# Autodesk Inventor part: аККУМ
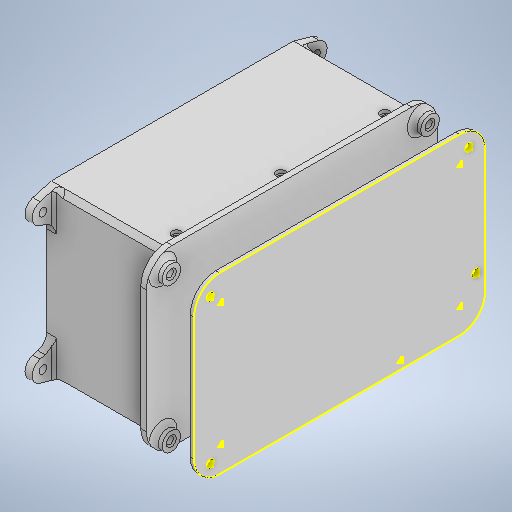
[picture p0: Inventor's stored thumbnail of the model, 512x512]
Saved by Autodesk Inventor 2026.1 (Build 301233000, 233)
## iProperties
Created: 2026-01
Part Number: аККУМ
Material: Типовые
Document SubType Name: Modeling
Designer: Yury Melnikov
Density: 1 g/cm^3
Appearance: По умолчанию
Author: Yury Melnikov
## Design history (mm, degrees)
sketch "Эскиз1"
  geometry: L1 (0, 0)-(65, 0); L2 (65, 0)-(65, 75); L3 (65, 75)-(0, 75); L4 (0, 75)-(0, 0); L5 (65, 0)-(0, 0); L6 (0, 0)-(0, -25); L7 (0, -25)-(65, -25); L8 (65, -25)-(65, 0); 1 further point
  constraints: 16 end point, 4 parallel, 2 horizontal, 2 perpendicular, 1 collinear
  dimensions: "d0" = 75 distance of L1.end L2.end; "d1" = 65 distance of L2.end L3.end; "d4" = 25 distance of L6.end L5.end
extrude "Выдавливание1" new body sketch "Эскиз1" distance "d2" = 45; taper "d3" = 0 deg
feature "Оболочка1" dims "d5" = 2.4
chamfer "Фаска1" distance "d9" = 2; stored, may be unused: second distance "d10" = 2, angle "d11" = 45 deg
sketch "Эскиз3"
  geometry: L1 (25, 63)-(25, 2) reference; L2 (23, 0)-(25, 2) reference; L3 (23, 0)-(-73, 0) reference; L4 (-75, 2)-(-73, 0) reference; L5 (-75, 2)-(-75, 63) reference; L6 (-73, 65)-(-75, 63) reference; L7 (-73, 65)-(23, 65) reference; L8 (25, 63)-(23, 65) reference; L9 (-75.4, -2.4)-(-77.4, -0.4) reference; L10 (-75.4, -2.4)-(25.4, -2.4) reference; L11 (27.4, -0.4)-(25.4, -2.4) reference; L12 (27.4, -0.4)-(27.4, 65.4) reference; L13 (25.4, 67.4)-(27.4, 65.4) reference; L14 (25.4, 67.4)-(-75.4, 67.4) reference; L15 (-77.4, 65.4)-(-75.4, 67.4) reference; L16 (-77.4, 65.4)-(-77.4, -0.4) reference; L17 (-72.917, 0.2)-(22.917, 0.2); L18 (22.917, 0.2)-(24.8, 2.083); L19 (24.8, 2.083)-(24.8, 62.917); L20 (24.8, 62.917)-(22.917, 64.8); L21 (22.917, 64.8)-(-72.917, 64.8); L22 (-72.917, 64.8)-(-74.8, 62.917); L23 (-74.8, 62.917)-(-74.8, 2.083); L24 (-74.8, 2.083)-(-72.917, 0.2); L25 (22.089, 2.2)-(-72.089, 2.2); L26 (-72.089, 2.2)-(-72.8, 2.911); L27 (-72.8, 2.911)-(-72.8, 62.089); L28 (-72.8, 62.089)-(-72.089, 62.8); L29 (-72.089, 62.8)-(22.089, 62.8); L30 (22.089, 62.8)-(22.8, 62.089); L31 (22.8, 62.089)-(22.8, 2.911); L32 (22.8, 2.911)-(22.089, 2.2); 1 further point
  constraints: 32 end point, 14 other
  dimensions: "d12" = 0.2 distance between parallel lines of L3 L17; "d13" = 2 distance between parallel lines of L17 L25
extrude "Выдавливание3" new body sketch "Эскиз3" distance "d14" = 5; taper "d15" = 0 deg
sketch "Эскиз4"
  geometry: L1 (25, 63)-(25, 2) reference; L2 (23, 0)-(25, 2) reference; L3 (23, 0)-(-73, 0) reference; L4 (-75, 2)-(-73, 0) reference; L5 (-75, 2)-(-75, 63) reference; L6 (-73, 65)-(-75, 63) reference; L7 (-73, 65)-(23, 65) reference; L8 (25, 63)-(23, 65) reference; L9 (-75.4, -2.4)-(-77.4, -0.4) reference; L10 (-75.4, -2.4)-(25.4, -2.4) reference; L11 (27.4, -0.4)-(25.4, -2.4) reference; L12 (27.4, -0.4)-(27.4, 65.4) reference; L13 (25.4, 67.4)-(27.4, 65.4) reference; L14 (25.4, 67.4)-(-75.4, 67.4) reference; L15 (-77.4, 65.4)-(-75.4, 67.4) reference; L16 (-77.4, 65.4)-(-77.4, -0.4) reference; 1 further point
extrude "Выдавливание4" join sketch "Эскиз4" distance "d16" = 2.4; taper "d17" = 0 deg
chamfer "Фаска2" distance "d18" = 2; stored, may be unused: second distance "d19" = 2, angle "d20" = 45 deg
chamfer "Фаска3" distance "d21" = 1.5; stored, may be unused: second distance "d22" = 2, angle "d23" = 45 deg
chamfer "Фаска4" distance "d24" = 0.5; stored, may be unused: second distance "d25" = 2, angle "d26" = 45 deg
sketch "Эскиз5"
  geometry: L1 (40.9, -98.317)-(40.9, -2.483) reference; L2 (45.4, -98.317)-(40.9, -98.317) reference; L3 (45.4, -2.483)-(45.4, -98.317) reference; L4 (45.4, -2.483)-(40.9, -2.483) reference; L5 (43.15, -93.817)-(43.15, -50.4); L6 (43.15, -50.4)-(43.15, -6.983); C1 r 0.75 at (43.15, -93.817); C2 r 0.75 at (43.15, -50.4); C3 r 0.75 at (43.15, -6.983); 3 further points
  constraints: 4 end point, 3 centre point, 2 collinear, 2 equal radius, 2 midpoint, 1 horizontal alignment, 1 point on line, 1 vertical
  dimensions: "d27" = 1.5 diameter of C2; "d28" = 4.5 distance from line of L2 L5.start
extrude "Выдавливание5" cut sketch "Эскиз5" distance "d29" = 75; taper "d30" = 0 deg
sketch "Эскиз8"
  geometry: L1 (-2.4, -2.4)-(98.4, -2.4) reference; L2 (-2.4, -2.4)-(72.6, -2.4); L3 (72.6, -2.4)-(72.6, 62.6); L4 (72.6, 62.6)-(-2.4, 62.6); L5 (-2.4, 62.6)-(-2.4, -2.4); L6 (74.6, -2.4)-(74.6, 62.6); L7 (72.6, -2.4)-(74.6, -2.4); L8 (72.6, 62.6)-(74.6, 62.6); L9 (74.6, 55.993)-(72.6, 55.993); L10 (72.6, 55.993)-(72.6, 64.22); L11 (72.6, 64.22)-(74.6, 64.22); L12 (74.6, 64.22)-(74.6, 55.993); 3 further points
  constraints: 22 end point, 5 parallel, 4 point on line, 3 horizontal, 2 perpendicular, 1 vertical
  dimensions: "d31" = 65 distance of L2.end L3.end; "d32" = 75 distance between parallel lines of L5 L3; "d33" = 2 distance between parallel lines of L6 L3
extrude "Выдавливание6" join sketch "Эскиз8" distance "d34" = 40; taper "d35" = 0 deg
chamfer "Фаска5" distance "d36" = 1; stored, may be unused: second distance "d37" = 2, angle "d38" = 45 deg
sketch "Эскиз9"
  geometry: L1 (0, 0)-(0, 65.8) reference; L2 (47.4, 0)-(0, 0) reference; L3 (15, 15)-(15, 50.8); C1 r 3 at (15, 15); C2 r 15 at (15, 15); C3 r 6.1 at (15, 50.8); 4 further points
  constraints: 3 centre point, 2 end point, 2 midpoint, 2 tangent, 1 coincident, 1 horizontal alignment, 1 vertical, 1 vertical alignment
  dimensions: "d39" = 6 diameter of C1; "d40" = 30 diameter of C2; "d41" = 12.2 diameter of C3
extrude "Выдавливание7" cut sketch "Эскиз9" distance "d42" = 3; taper "d43" = 0 deg
sketch "Эскиз10"
  geometry: L1 (40.4, -74)-(2.4, -74) reference; L2 (40.4, -74)-(40.4, -78) reference; L3 (2.4, -78)-(40.4, -78) reference; L4 (2.4, -98.4)-(2.4, -78) reference; L5 (45.4, -98.4)-(2.4, -98.4) reference; L6 (45.4, -2.4)-(45.4, -98.4) reference; L7 (2.4, -2.4)-(45.4, -2.4) reference; L8 (2.4, -74)-(2.4, -2.4) reference; L9 (31.65, -83.95)-(16.15, -83.95); L10 (16.15, -83.95)-(16.15, -92.45); L11 (16.15, -92.45)-(31.65, -92.45); L12 (31.65, -92.45)-(31.65, -83.95); C1 r 0.75 at (43.15, -93.817) reference; C2 r 0.75 at (43.15, -50.4) reference; C3 r 0.75 at (43.15, -6.983) reference; 5 further points
  constraints: 8 end point, 4 midpoint, 2 parallel, 1 horizontal, 1 horizontal alignment, 1 perpendicular, 1 vertical alignment
  dimensions: "d44" = 15.5 distance of L11.end L10.end; "d45" = 8.5 distance of L10.end L9.end
extrude "Выдавливание8" cut sketch "Эскиз10" distance "d46" = 3; taper "d47" = 0 deg
chamfer "Фаска6" distance "d48" = 0.7; stored, may be unused: second distance "d49" = 2, angle "d50" = 45 deg
chamfer "Фаска7" distance "d51" = 0.5; stored, may be unused: second distance "d52" = 2, angle "d53" = 45 deg
sketch "Эскиз11"
  geometry: C1 r 0.75 at (43.15, -6.983) reference; C2 r 0.75 at (43.15, -50.4) reference; C3 r 0.75 at (43.15, -93.817) reference; C4 r 2 at (43.15, -6.983); C5 r 2 at (43.15, -50.4); C6 r 2 at (43.15, -93.817); 1 further point
  constraints: 3 centre point, 2 equal radius
  dimensions: "d54" = 4 diameter of C4
extrude "Выдавливание9" cut sketch "Эскиз11" distance "d55" = 1.4; taper "d56" = 0 deg
chamfer "Фаска8" distance "d57" = 0.5; stored, may be unused: second distance "d58" = 2, angle "d59" = 45 deg
node "РабПлоскость2"
mirror "Зеркальное отражение1"
node "РабПлоскость3"
sketch "Эскиз12"
  geometry: L1 (2, 61)-(2, 0) reference; L2 (2, 0)-(2, 61) reference; L3 (2, 9.6)-(2, 15.6) reference; L4 (2, 42.3)-(2, 54.5) reference; L5 (2, 49)-(-4.5, 49); L6 (-4.5, 49)-(-4.5, 42); L7 (-4.5, 42)-(-2.5, 42); L8 (-2.5, 42)-(-2.5, 47); L9 (-2.5, 47)-(2, 47); L10 (-2.5, 47)-(-2.5, 49); L11 (2, 30.5)-(16.292, 30.5); L12 (2, 18.7)-(2, 6.5); L13 (2, 12)-(-4.5, 12); L14 (-4.5, 12)-(-4.5, 19); L15 (-4.5, 19)-(-2.5, 19); L16 (-2.5, 19)-(-2.5, 14); L17 (-2.5, 14)-(2, 14); L18 (-2.5, 14)-(-2.5, 12); 6 further points
  constraints: 28 end point, 9 symmetric about line, 8 point on line, 3 horizontal, 3 perpendicular, 2 midpoint, 1 vertical
  dimensions: "d62" = 5 distance of L7.end L8.end; "d63" = 2 distance of L6.end L7.end; "d64" = 4.5 distance of L8.end L9.end; "d65" = 33 distance from line of L17 point (-0.25, 47)
extrude "Выдавливание10" join sketch "Эскиз12" distance "d66" = 6; taper "d67" = 0 deg
sketch "Эскиз13"
  geometry: L1 (37, 16.4)-(37, 21.4) reference; L2 (37, 21.4)-(31, 21.4) reference; L3 (31, 16.4)-(31, 21.4) reference; L4 (37, 16.4)-(31, 16.4) reference; L5 (37, 44.4)-(37, 49.4) reference; L6 (37, 49.4)-(31, 49.4) reference; L7 (31, 44.4)-(31, 49.4) reference; L8 (37, 44.4)-(31, 44.4) reference; L9 (27.35, 16.65)-(40.65, 16.65); L10 (40.65, 16.65)-(40.65, 49.15); L11 (40.65, 49.15)-(27.35, 49.15); L12 (27.35, 49.15)-(27.35, 16.65); L13 (31, 21.4)-(31, 44.4); C1 r 1.65 at (30.35, 41.15); C2 r 1.65 at (30.35, 36.15); C3 r 1.65 at (30.35, 31.15); C4 r 1.65 at (30.35, 26.15); C5 r 2.1 at (35.65, 41.65); 5 further points
  constraints: 10 end point, 5 centre point, 4 midpoint, 2 parallel, 2 vertical, 1 horizontal, 1 horizontal alignment, 1 perpendicular, 1 vertical alignment, 6 other
  dimensions: "d68" = 32.5 distance of L11.end L9.start; "d69" = 13.3 distance of L9.start L9.end; "d70" = 3 horizontal distance of C1.centre L11.end; "d71" = 8 vertical distance of L11.end C1.centre; "d72" = 3.3 diameter of C1; "d75" = 5 distance of C1.centre C2.centre; "d80" = 4.2 diameter of C5; "d81" = 7.5 vertical distance of L10.end C5.centre; "d82" = 5 distance from line of L10 C5.centre
extrude "Выдавливание11" cut sketch "Эскиз13" distance "d83" = 6; taper "d84" = 0 deg
chamfer "Фаска9" distance "d85" = 0.5; stored, may be unused: second distance "d86" = 2, angle "d87" = 45 deg
chamfer "Фаска10" distance "d88" = 3; stored, may be unused: second distance "d89" = 2, angle "d90" = 45 deg
sketch "Эскиз15"
  geometry: L1 (-77.4, 67.4)-(27.4, 67.4); L2 (27.4, 67.4)-(27.4, -2.4); L3 (27.4, -2.4)-(-77.4, -2.4); L4 (-77.4, -2.4)-(-77.4, 67.4); L5 (25.4, 67.4)-(-75.4, 67.4) reference; L6 (-77.4, 65.4)-(-77.4, -0.4) reference; L7 (-75.4, -2.4)-(25.4, -2.4) reference; L8 (27.4, -0.4)-(27.4, 65.4) reference; 1 further point
  constraints: 8 end point, 4 collinear, 2 parallel, 1 horizontal, 1 perpendicular
  dimensions: "d99" = 104.8 distance of L1.start L1.end (derived); "d100" = 69.8 distance of L1.end L2.end (derived)
sketch "Эскиз16"
  geometry: L1 (-2.4, -2)-(47.4, -2); L2 (47.4, -2)-(47.4, 67.8); L3 (47.4, 67.8)-(-2.4, 67.8); L4 (-2.4, 67.8)-(-2.4, -2); L5 (47.4, 67.8)-(0, 67.8) reference; L6 (47.4, 0)-(47.4, 65.8) reference; L7 (-2.4, 64.972)-(-2.4, 0.828) reference; L8 (0, -2)-(47.4, -2) reference; 3 further points
  constraints: 8 end point, 4 collinear, 2 parallel, 1 horizontal, 1 perpendicular
  dimensions: "d101" = 49.8 distance of L2.end L3.end (derived)
sketch "Эскиз17"
  geometry: L1 (15.4, 55.4)-(15.4, 9.6); L2 (15.4, 9.6)-(-65.4, 32.5); L3 (27.4, -0.4)-(27.4, 65.4) reference; L4 (-74.572, 65.4)-(24.572, 65.4) reference; L5 (25.4, 64.572)-(25.4, 0.428) reference; L6 (24.572, -0.4)-(-74.572, -0.4) reference; L7 (-75.4, 0.428)-(-75.4, 64.572) reference; C1 r 2 at (-65.4, 32.5); C2 r 2 at (15.4, 55.4); C3 r 2 at (15.4, 9.6); C4 r 10 at (15.4, 55.4); C5 r 10 at (15.4, 9.6); C6 r 10 at (-65.4, 32.5); 3 further points
  constraints: 6 centre point, 4 end point, 4 tangent, 3 coincident, 3 equal radius, 2 horizontal alignment, 2 midpoint, 1 vertical, 1 vertical alignment
  dimensions: "d102" = 4 diameter of C1; "d103" = 8 distance edge to line of C1 L7
extrude "Выдавливание13" cut sketch "Эскиз17" distance "d104" = 10; taper "d105" = 0 deg
sketch "Эскиз20"
  geometry: L1 (-25.4, 67.4)-(75.4, 67.4) reference; L2 (-27.4, -2.4)-(-27.4, 67.4) reference; L3 (-47.022, 65.4)-(-10.668, 65.4); L4 (-58.591, -0.4)-(13.104, -0.4); L5 (77.4, 65.4)-(77.4, -0.4) reference; L6 (75.4, 67.4)-(83.117, 65.232); L7 (83.117, 56.568)-(77.4, 54.962); L8 (83.117, 65.232)-(77.4, 66.838); L9 (25, 67.4)-(25, 80.723); L10 (77.4, 32.5)-(86.793, 32.5); L11 (-25.4, 67.4)-(-33.117, 65.232); L12 (-33.117, 56.568)-(-27.4, 54.962); L13 (-47.022, -0.4)-(-10.668, -0.4); L14 (-33.117, 8.432)-(-27.4, 10.038); L15 (-25.4, -2.4)-(-33.117, -0.232); L16 (-25.4, -2.4)-(75.4, -2.4); L17 (83.117, 8.432)-(77.4, 10.038); L18 (83.117, -0.232)-(77.4, -1.838); L19 (75.4, -2.4)-(83.117, -0.232); L20 (-27.4, 65.4)-(-25.4, 67.4) reference; L21 (-27.4, -0.4)-(-27.4, 65.4) reference; L22 (-25.4, -2.4)-(-27.4, -0.4) reference; L23 (75.4, -2.4)-(-25.4, -2.4) reference; L24 (77.4, -0.4)-(75.4, -2.4) reference; L25 (77.4, 65.4)-(77.4, -0.4) reference; L26 (75.4, 67.4)-(77.4, 65.4) reference; L27 (-25.4, 67.4)-(75.4, 67.4) reference; C1 r 1.65 at (-31.9, 60.9); C2 r 4.5 at (-31.9, 60.9); C3 r 1.65 at (81.9, 60.9); C4 r 1.65 at (-31.9, 4.1); C5 r 4.5 at (-31.9, 4.1); C6 r 1.65 at (81.9, 4.1); C7 r 4.5 at (81.9, 4.1); C8 r 4.5 at (-31.9, 4.1); C9 r 1.65 at (-31.9, 4.1); C10 r 1.65 at (81.9, 4.1); A1 r 4.5 centre (81.9, 60.9) between (83.117, 56.568) and (83.117, 65.232); A2 r 5.938 centre (77.4, 60.9) between (77.4, 66.838) and (77.4, 54.962); A3 r 4.5 centre (81.9, 4.1) between (83.117, 8.432) and (83.117, -0.232); A4 r 5.938 centre (77.4, 4.1) between (77.4, -1.838) and (77.4, 10.038); 21 further points
  constraints: 32 end point, 20 symmetric about line, 14 centre point, 10 point on circle, 8 point on line, 6 coincident, 6 tangent, 4 horizontal, 2 midpoint, 2 vertical, 1 collinear, 17 other
  dimensions: "d122" = 3.3 diameter of C1; "d123" = 9 diameter of C2; "d126" = 113.8 distance of C1.centre C3.centre (derived); "d129" = 56.8 distance of C1.centre C4.centre (derived)
extrude "Выдавливание16" join sketch "Эскиз20" distance "d132" = 3; taper "d133" = 0 deg
fillet "Сопряжение1" dims "d134" = 5
node "РабПлоскость5"
chamfer "Фаска12" distance "d135" = 1; stored, may be unused: second distance "d136" = 2, angle "d137" = 45 deg
sketch "Эскиз21"
  geometry: L1 (-31.9, 60.9)-(81.9, 60.9); L2 (81.9, 60.9)-(81.9, 4.1); L3 (81.9, 4.1)-(-31.9, 4.1); L4 (-31.9, 4.1)-(-31.9, 60.9); C1 r 1.65 at (-31.9, 60.9) reference; C2 r 1.65 at (81.9, 4.1) reference; 1 further point
  constraints: 8 end point, 2 parallel, 1 horizontal, 1 perpendicular
  dimensions: "d138" = 56.8 distance of L1.end L2.end (derived); "d139" = 113.8 distance of L1.start L1.end (derived)
sketch "Эскиз22"
  geometry: L1 (-74.911, 68.773)-(24.911, 68.773); L2 (-85.594, 58.09)-(-85.594, 6.909); L3 (-74.911, -3.774)-(24.911, -3.774); L4 (35.594, 6.909)-(35.594, 58.09); L5 (-75.4, 0.428)-(-75.4, 64.572) reference; L6 (-74.572, -0.4)-(-75.4, 0.428) reference; L7 (24.572, -0.4)-(-74.572, -0.4) reference; L8 (25.4, 0.428)-(24.572, -0.4) reference; L9 (25.4, 64.572)-(25.4, 0.428) reference; L10 (24.572, 65.4)-(25.4, 64.572) reference; L11 (-74.572, 65.4)-(24.572, 65.4) reference; L12 (-75.4, 64.572)-(-74.572, 65.4) reference; L13 (24.572, 65.4)-(25.4, 65.4); L14 (25.4, 65.4)-(25.4, 64.572); L15 (-74.572, 65.4)-(-75.4, 65.4); L16 (-75.4, 65.4)-(-75.4, 64.572); L17 (-75.4, 0.428)-(-77.4, -0.4) reference; L18 (-75.4, 0.428)-(-75.4, -0.4); L19 (-75.4, -0.4)-(-74.572, -0.4); C1 r 1.5 at (-78.848, 62.155); C2 r 1.5 at (28.848, 62.155); C3 r 1.5 at (-78.848, 1.957); C4 r 1.5 at (31.738, 15.419); C5 r 66.772 at (-25, 32.5); C6 r 2 at (15.4, 55.4) reference; C7 r 2 at (15.4, 9.6) reference; C8 r 2 at (-65.4, 32.5) reference; A1 r 10.683 centre (-74.911, 58.09) between (-74.911, 68.773) and (-85.594, 58.09); A2 r 10.683 centre (-74.911, 6.909) between (-85.594, 6.909) and (-74.911, -3.774); A3 r 10.683 centre (24.911, 6.909) between (24.911, -3.774) and (35.594, 6.909); A4 r 10.683 centre (24.911, 58.09) between (35.594, 58.09) and (24.911, 68.773); A5 r 60.188 centre (-25, 32.5) between (25.4, 65.4) and (-75.4, 65.4); 5 further points
  constraints: 20 end point, 11 point on circle, 11 tangent, 10 centre point, 4 coincident, 4 perpendicular, 3 equal radius, 3 horizontal, 3 vertical, 2 point on line, 1 concentric, 1 horizontal alignment, 1 vertical alignment
  dimensions: "d140" = 60.198 distance of point (-78.848, 1.957) point (-78.848, 62.155); "d141" = 107.696 distance of point (28.848, 62.155) point (-78.848, 62.155); "d142" = 110.586 horizontal distance of point (31.738, 15.419) point (-78.848, 62.155); "d143" = 46.736 vertical distance of point (-78.848, 62.155) point (31.738, 15.419); "d144" = 3 diameter of C1; "d145" = 3.937 horizontal distance of C1.centre A1.centre; "d146" = -4.064 vertical distance of C1.centre A1.centre; "d147" = 10.683 radius of A1; "d148" = 51.181 distance of L2.start L2.end; "d149" = 10.683 radius of A2; "d150" = 99.822 distance of L3.start L3.end; "d151" = 10.683 radius of A3; "d152" = 10.683 radius of A4
extrude "Выдавливание17" new body sketch "Эскиз22" distance "d153" = 1.6; taper "d154" = 0 deg
sketch "Эскиз23"
  geometry: L1 (85.594, 58.09)-(85.594, 6.909) reference; L2 (-24.911, 68.773)-(74.911, 68.773) reference; L3 (-35.594, 6.909)-(-35.594, 58.09) reference; L4 (74.911, -3.774)-(-24.911, -3.774) reference; C1 r 1.5 at (-31.738, 15.419) reference; C2 r 1.5 at (78.848, 1.957) reference; C3 r 1.5 at (-28.848, 62.155) reference; C4 r 1.5 at (78.848, 62.155) reference; C5 r 2 at (-15.4, 55.4) reference; C6 r 2 at (65.4, 32.5) reference; C7 r 2 at (-15.4, 9.6) reference; A1 r 10.683 centre (74.911, 58.09) between (85.594, 58.09) and (74.911, 68.773) reference; A2 r 10.683 centre (-24.911, 58.09) between (-24.911, 68.773) and (-35.594, 58.09) reference; A3 r 10.683 centre (-24.911, 6.909) between (-35.594, 6.909) and (-24.911, -3.774) reference; A4 r 10.683 centre (74.911, 6.909) between (74.911, -3.774) and (85.594, 6.909) reference; 1 further point
extrude "Выдавливание18" join sketch "Эскиз23" stored distance "d155" = 1.6; taper "d156" = 0 deg
sketch "Эскиз24"
  geometry: C1 r 1.5 at (31.738, 15.419) reference; C2 r 1.5 at (28.848, 62.155) reference; C3 r 1.5 at (-78.848, 1.957) reference; C4 r 1.5 at (-78.848, 62.155) reference; C5 r 1.5 at (-78.848, 1.957); C6 r 1.5 at (-78.848, 62.155); C7 r 1.5 at (28.848, 62.155); C8 r 1.5 at (31.738, 15.419); 1 further point
  constraints: 4 centre point, 3 equal radius
  dimensions: "d157" = 3 diameter of C8
extrude "Выдавливание19" cut sketch "Эскиз24" distance "d158" = 10; taper "d159" = 0 deg
sketch "Эскиз25"
  geometry: L1 (-35.594, 58.09)-(-35.594, 6.909) reference; L2 (-24.911, -3.774)-(74.911, -3.774) reference; L3 (85.594, 6.909)-(85.594, 58.09) reference; L4 (74.911, 68.773)-(-24.911, 68.773) reference; L5 (-24.8, 2.083)-(-24.8, 62.917) reference; L6 (-24.8, 62.917)-(-22.917, 64.8) reference; L7 (-22.917, 64.8)-(72.917, 64.8) reference; L8 (72.917, 64.8)-(74.8, 62.917) reference; L9 (74.8, 62.917)-(74.8, 2.083) reference; L10 (74.8, 2.083)-(72.917, 0.2) reference; L11 (72.917, 0.2)-(-22.917, 0.2) reference; L12 (-22.917, 0.2)-(-24.8, 2.083) reference; L13 (-35.594, 58.09)-(-35.594, 6.909) reference; L14 (-35.594, 58.09)-(-35.594, 6.909) reference; L15 (74.911, 68.773)-(-24.911, 68.773) reference; L16 (85.594, 6.909)-(85.594, 58.09) reference; L17 (-24.911, -3.774)-(74.911, -3.774) reference; C1 r 3.856 at (-31.738, 15.419); C2 r 3.856 at (-28.848, 62.155); C3 r 3.856 at (78.848, 62.155); C4 r 3.856 at (78.848, 1.957); C5 r 1.5 at (78.848, 62.155) reference; C6 r 1.5 at (78.848, 1.957) reference; C7 r 1.5 at (-28.848, 62.155) reference; C8 r 1.5 at (-31.738, 15.419) reference; C9 r 2 at (-15.4, 55.4) reference; C10 r 2 at (-15.4, 9.6) reference; C11 r 2 at (65.4, 32.5) reference; A1 r 10.683 centre (-24.911, 58.09) between (-24.911, 68.773) and (-35.594, 58.09) reference; A2 r 10.683 centre (-24.911, 6.909) between (-35.594, 6.909) and (-24.911, -3.774) reference; A3 r 10.683 centre (74.911, 6.909) between (74.911, -3.774) and (85.594, 6.909) reference; A4 r 10.683 centre (74.911, 58.09) between (85.594, 58.09) and (74.911, 68.773) reference; A5 r 10.683 centre (-24.911, 58.09) between (-24.911, 68.773) and (-35.594, 58.09) reference; A6 r 10.683 centre (74.911, 58.09) between (85.594, 58.09) and (74.911, 68.773) reference; A7 r 10.683 centre (74.911, 6.909) between (74.911, -3.774) and (85.594, 6.909) reference; A8 r 10.683 centre (-24.911, 6.909) between (-35.594, 6.909) and (-24.911, -3.774) reference; 1 further point
  constraints: 4 centre point, 3 equal radius, 1 tangent
extrude "Выдавливание20" join sketch "Эскиз25" distance "d161" = 6; taper "d162" = 0 deg
fillet "Сопряжение2" dims "d163" = 2
chamfer "Фаска13" distance "d164" = 0.6; stored, may be unused: second distance "d165" = 2, angle "d166" = 45 deg
sketch "Эскиз26"
  geometry: L1 (-74.911, 68.773)-(24.911, 68.773) reference; L2 (-85.594, 6.909)-(-85.594, 58.09) reference; L3 (24.911, -3.774)-(-74.911, -3.774) reference; L4 (35.594, 11.011)-(35.594, 6.909) reference; L5 (35.594, 58.09)-(35.594, 19.826) reference; C1 r 2 at (-65.4, 32.5) reference; C2 r 2 at (15.4, 9.6) reference; C3 r 2 at (15.4, 55.4) reference; A1 r 5.856 centre (28.848, 62.155) between (28.876, 68.01) and (34.7, 62.368) reference; A2 r 10.683 centre (24.911, 58.09) between (28.876, 68.01) and (24.911, 68.773) reference; A3 r 10.683 centre (-74.911, 58.09) between (-74.911, 68.773) and (-78.876, 68.01) reference; A4 r 5.856 centre (-78.848, 62.155) between (-84.7, 62.368) and (-78.876, 68.01) reference; A5 r 10.683 centre (-74.911, 58.09) between (-84.7, 62.368) and (-85.594, 58.09) reference; A6 r 10.683 centre (-74.911, 6.909) between (-85.594, 6.909) and (-84.672, 2.568) reference; A7 r 5.856 centre (-78.848, 1.957) between (-76.938, -3.579) and (-84.672, 2.568) reference; A8 r 10.683 centre (-74.911, 6.909) between (-76.938, -3.579) and (-74.911, -3.774) reference; A9 r 10.683 centre (24.911, 6.909) between (24.911, -3.774) and (35.594, 6.909) reference; A10 r 5.856 centre (31.738, 15.419) between (35.594, 19.826) and (35.594, 11.011) reference; A11 r 10.683 centre (24.911, 58.09) between (35.594, 58.09) and (34.7, 62.368) reference; 1 further point
extrude "Выдавливание21" join sketch "Эскиз26" stored distance "d167" = 6; taper "d168" = 0 deg
sketch "Эскиз28"
  geometry: C1 r 0.75 at (-2.25, 4.5) reference; C2 r 0.75 at (-2.25, 47.917) reference; C3 r 0.75 at (-2.25, 91.334) reference; 1 further point
sketch "Эскиз29"
  geometry: L1 (-19.167, 2.2)-(-17.667, 2.2) reference; L2 (24.25, 2.2)-(25.75, 2.2) reference; L3 (67.667, 2.2)-(69.167, 2.2) reference; L4 (69.167, 62.8)-(67.667, 62.8) reference; L5 (25.75, 62.8)-(24.25, 62.8) reference; L6 (-17.667, 62.8)-(-19.167, 62.8) reference; L7 (-20.667, 2.2)-(-16.167, 2.2); L8 (-16.167, 2.2)-(-16.167, 6.2); L9 (-16.167, 6.2)-(-20.667, 6.2); L10 (-20.667, 6.2)-(-20.667, 2.2); L11 (27.25, 2.2)-(27.25, 6.2); L12 (22.75, 2.2)-(27.25, 2.2); L13 (22.75, 6.2)-(22.75, 2.2); L14 (27.25, 6.2)-(22.75, 6.2); L15 (70.667, 2.2)-(70.667, 6.2); L16 (66.167, 2.2)-(70.667, 2.2); L17 (66.167, 6.2)-(66.167, 2.2); L18 (70.667, 6.2)-(66.167, 6.2); L19 (71.3, 61.3)-(71.3, 3.7) reference; L20 (71.3, 32.5)-(55.911, 32.5); L21 (67.667, 62.8)-(69.167, 62.8); L22 (66.167, 58.8)-(66.167, 62.8); L23 (66.167, 62.8)-(70.667, 62.8); L24 (70.667, 62.8)-(70.667, 58.8); L25 (70.667, 58.8)-(66.167, 58.8); L26 (-16.167, 62.8)-(-16.167, 58.8); L27 (-20.667, 62.8)-(-16.167, 62.8); L28 (-16.167, 58.8)-(-20.667, 58.8); L29 (-20.667, 58.8)-(-20.667, 62.8); L30 (-19.167, 62.8)-(-17.667, 62.8); L31 (24.25, 62.8)-(25.75, 62.8); L32 (27.25, 62.8)-(27.25, 58.8); L33 (22.75, 58.8)-(22.75, 62.8); L34 (22.75, 62.8)-(27.25, 62.8); L35 (27.25, 58.8)-(22.75, 58.8); 30 further points
  constraints: 56 end point, 21 symmetric about line, 8 horizontal alignment, 6 parallel, 5 midpoint, 4 collinear, 3 horizontal, 2 vertical alignment, 1 perpendicular, 6 other
  dimensions: "d174" = 43.41716 distance of L7.end L11.start (derived); "d179" = 1.5 distance from line of L10 L1.start; "d180" = 4 distance of L9.end L7.start
extrude "Выдавливание23" join sketch "Эскиз29" stored distance "d181" = 10; taper "d182" = 0 deg
extrude "Выдавливание24" cut sketch "Эскиз28" stored distance "d183" = 10; taper "d184" = 0 deg
fillet "Сопряжение3" dims "d185" = 2
chamfer "Фаска14" distance "d186" = 0.6; stored, may be unused: second distance "d187" = 2, angle "d188" = 45 deg
sketch "Эскиз31"
  geometry: L1 (-85.594, 58.09)-(-85.594, 6.909) reference; L2 (-74.911, -3.774)-(24.911, -3.774) reference; L3 (35.594, 6.909)-(35.594, 58.09) reference; L4 (24.911, 68.773)-(-74.911, 68.773) reference; C1 r 1.5 at (31.738, 15.419) reference; C2 r 1.5 at (-78.848, 1.957) reference; C3 r 1.5 at (28.848, 62.155) reference; C4 r 1.5 at (-78.848, 62.155) reference; A1 r 10.683 centre (-74.911, 6.909) between (-85.594, 6.909) and (-74.911, -3.774) reference; A2 r 10.683 centre (24.911, 6.909) between (24.911, -3.774) and (35.594, 6.909) reference; A3 r 10.683 centre (24.911, 58.09) between (35.594, 58.09) and (24.911, 68.773) reference; A4 r 10.683 centre (-74.911, 58.09) between (-74.911, 68.773) and (-85.594, 58.09) reference; 1 further point
  node "Спроецированная петля19"
feature "ݼ耀ݾ耀ހ耀ނ耀ބ耀ކ耀ވ耀ފ耀" dims "d0" = 75, "d1" = 65, "d2" = 45, "d3" = 0, "d4" = 25, "d5" = 2.4, "d9" = 2, "d10" = 2, "d11" = 45 deg, "d12" = 0.2, "d13" = 2, "d14" = 5, "d15" = 0, "d16" = 2.4, "d17" = 0, "d18" = 2, "d19" = 2, "d20" = 45 deg, "d21" = 1.5, "d22" = 2, "d23" = 45 deg, "d24" = 0.5, "d25" = 2, "d26" = 45 deg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
feature "ม耀ร耀ล耀ว耀ษ耀ห耀อ耀ฯ耀" dims "d0" = 75, "d1" = 65, "d2" = 45, "d3" = 0, "d4" = 25, "d5" = 2.4, "d9" = 2, "d10" = 2, "d11" = 45 deg, "d12" = 0.2, "d13" = 2, "d14" = 5, "d15" = 0, "d16" = 2.4, "d17" = 0, "d18" = 2, "d19" = 2, "d20" = 45 deg, "d21" = 1.5, "d22" = 2, "d23" = 45 deg, "d24" = 0.5, "d25" = 2, "d26" = 45 deg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
node "Твердое тело1"
node "Спроецированная петля2"
node "Твердое тело2"
node "Спроецированная петля3"
node "Спроецированная петля4"
node "Спроецированная петля5"
node "Спроецированная петля6"
node "Спроецированная петля7"
node "Спроецированная петля8"
node "Эскиз — прямоугольный массив1" dims "d75" = 5, "d78" = 10
node "Эскиз — прямоугольный массив3" dims "d126" = 113.8 (derived), "d129" = 56.8 (derived)
node "Спроецированная петля11"
node "Спроецированная петля12"
node "Плаьа"
node "Спроецированная петля13"
node "Спроецированная петля14"
node "Спроецированная петля15"
node "Эскиз — прямоугольный массив4" dims "d174" = 43.41716 (derived), "d177" = 10
node "Спроецированная петля17"
